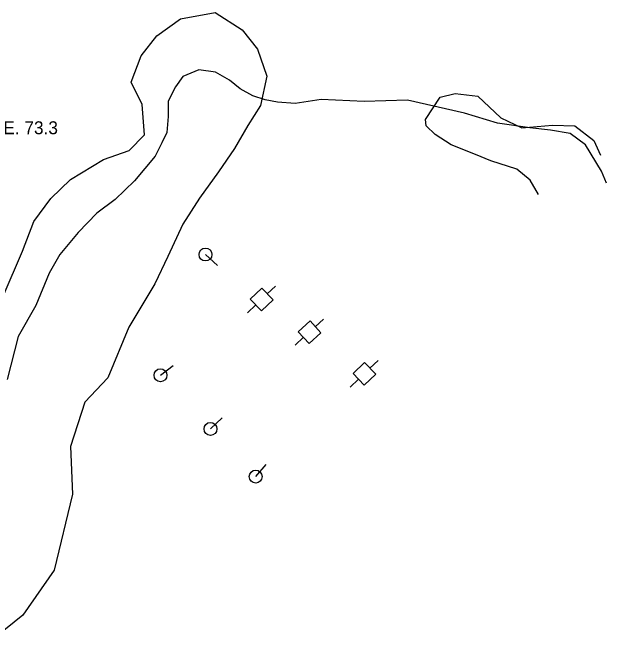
# Model space of a CAD drawing. Extents: x 2161152 to 2175754, y 602179 to 617749.
# Drawn here: x 2165388.5 to 2165572.8, y 606891.6 to 607087.8 of the extents above; entities that cross this region are included whole.
import ezdxf

# ---------------------------------------------------------------- set-up
doc = ezdxf.new("R2010")
doc.units = 0
for name, color, linetype in [('RD_EX_H2O', 7, 'Continuous'), ('RD_EX_H2O_txCode', 7, 'Continuous'), ('RD_EX_UT', 7, 'Continuous'), ('RD_EX_VEG', 7, 'Continuous')]:
    doc.layers.add(name, color=color, linetype=linetype)

msp = doc.modelspace()

# ---------------------------------------------------------------- linework, layer by layer
at = {"layer": 'RD_EX_H2O'}
msp.add_lwpolyline([(2165572.75, 607034.82), (2165571.28, 607038.57), (2165566.24, 607046.72), (2165561.5, 607050.27), (2165555.39, 607051.29), (2165548.95, 607052.02), (2165538.98, 607053.41), (2165528.73, 607056.58), (2165511.03, 607060.6), (2165497.57, 607060.16), (2165484.18, 607060.77), (2165476.17, 607059.52), (2165470.7, 607059.93), (2165466.85, 607060.69), (2165462.99, 607061.97), (2165459.13, 607064.14), (2165455.72, 607066.81), (2165451.44, 607069.27), (2165446.3, 607069.98), (2165441.27, 607067.93), (2165438.97, 607064.78), (2165436.72, 607060.26), (2165436.7, 607055.52), (2165436.28, 607050.56), (2165434.8, 607047.33), (2165432.69, 607043.23), (2165426.23, 607035.53), (2165420.28, 607029.72), (2165414.56, 607025.55), (2165408.8, 607019.54), (2165403.15, 607012.67), (2165399.79, 607006.9), (2165395.61, 606996.78), (2165390.12, 606987.23), (2165386.77, 606973.82)], dxfattribs=at)
at = {"layer": 'RD_EX_UT'}
for p, q in [((2165448.31, 607012.66), (2165452, 607009.28)), ((2165465.84, 607002.22), (2165462.22, 606998.78)), ((2165469.28, 606998.6), (2165465.84, 607002.22)), ((2165470.01, 607002.82), (2165467.49, 607000.43)), ((2165462.22, 606998.78), (2165465.66, 606995.16)), ((2165465.66, 606995.16), (2165469.28, 606998.6)), ((2165463.95, 606997.06), (2165461.31, 606994.55)), ((2165480.79, 606992.06), (2165477.1, 606988.69)), ((2165484.16, 606988.37), (2165480.79, 606992.06)), ((2165484.97, 606992.57), (2165482.41, 606990.23)), ((2165477.1, 606988.69), (2165480.47, 606984.99)), ((2165480.47, 606984.99), (2165484.16, 606988.37)), ((2165478.79, 606986.94), (2165476.11, 606984.48)), ((2165434.34, 606975.17), (2165438.29, 606978.23)), ((2165497.72, 606979.15), (2165494.11, 606975.68)), ((2165501.18, 606975.54), (2165497.72, 606979.15)), ((2165501.88, 606979.77), (2165499.38, 606977.36)), ((2165494.11, 606975.68), (2165497.58, 606972.08)), ((2165497.58, 606972.08), (2165501.18, 606975.54)), ((2165495.85, 606973.97), (2165493.23, 606971.45)), ((2165449.86, 606958.5), (2165453.49, 606961.94)), ((2165463.9, 606943.69), (2165467.2, 606947.44))]:
    msp.add_line(p, q, dxfattribs=at)
for centre in [(2165448.31, 607012.66), (2165434.34, 606975.17), (2165449.86, 606958.5), (2165463.9, 606943.69)]:
    msp.add_circle(centre, 2, dxfattribs=at)
at = {"layer": 'RD_EX_VEG'}
for points in [[(2165385.49, 606999.68), (2165391.48, 607013.74), (2165394.99, 607022.91), (2165400.35, 607030.05), (2165406.4, 607035.94), (2165416.64, 607042.16), (2165424.62, 607044.96), (2165429.41, 607049.86), (2165428.67, 607059.27), (2165425.23, 607066.22), (2165428.34, 607074.36), (2165433.23, 607080.55), (2165440.55, 607085.8), (2165451.3, 607087.78), (2165459.7, 607082.43), (2165464.43, 607076.43), (2165467.33, 607068.09), (2165465.35, 607058.96), (2165461.43, 607052.7), (2165457.36, 607045.62), (2165452.38, 607038.31), (2165446.5, 607030.18), (2165441.33, 607022.1), (2165436.58, 607012.01), (2165432.6, 607003.53), (2165424.54, 606990.12), (2165417.96, 606974.38), (2165410.82, 606966.82), (2165406.37, 606953.05), (2165407.02, 606938.27), (2165401.34, 606914.58), (2165391.66, 606900.66), (2165380.25, 606891.59)], [(2165551.72, 607031.25), (2165549.07, 607035.78), (2165545.01, 607039.17), (2165536.93, 607041.8), (2165532.13, 607043.7), (2165524.57, 607046.74), (2165519.64, 607049.94), (2165516.83, 607052.61), (2165516.61, 607054.57), (2165521.15, 607061.49), (2165525.82, 607062.68), (2165532.9, 607061.81), (2165540.03, 607055.07), (2165546.51, 607052), (2165556.06, 607052.85), (2165562.97, 607052.58), (2165568.87, 607048.08), (2165570.97, 607043.49)]]:
    msp.add_lwpolyline(points, dxfattribs=at)

# ---------------------------------------------------------------- texts
at = {"layer": 'RD_EX_H2O_txCode'}
msp.add_text('W.E. 73.3', height=4, dxfattribs=at).set_placement((2165379.03, 607050.03))

doc.saveas('drawing.dxf')
